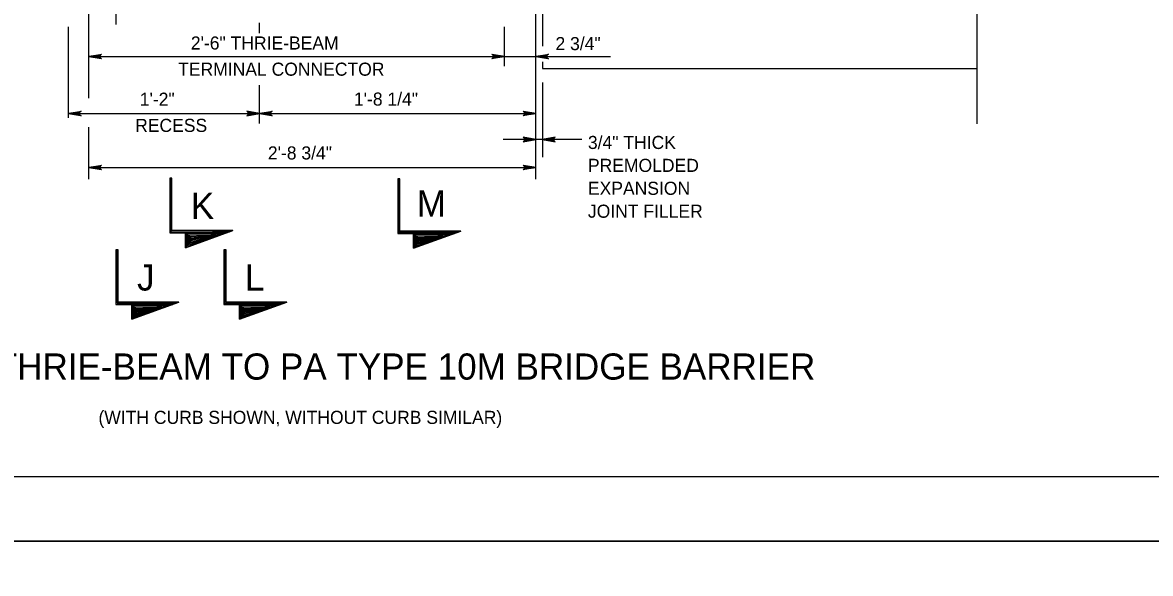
# Model space of a CAD drawing. Extents: x 632007860 to 635435983, y 295418622 to 297794622.
# Drawn here: x 633850541 to 634113016, y 296599122 to 296727373 of the extents above; entities that cross this region are included whole.
import ezdxf

# ---------------------------------------------------------------- set-up
doc = ezdxf.new("R2010")
doc.units = 0
for name, color, linetype in [('1', 7, 'Continuous'), ('PLT-BNDY', 7, 'Continuous'), ('S-DETL-DIMS', 7, 'Continuous'), ('S-DETL-T120', 7, 'Continuous'), ('S-DETL-T240', 7, 'Continuous'), ('S-STEL', 7, 'Continuous')]:
    doc.layers.add(name, color=color, linetype=linetype)

msp = doc.modelspace()

# ---------------------------------------------------------------- linework, layer by layer
at = {"layer": '1'}
msp.add_line((634515860, 296621622), (633729860, 296621622), dxfattribs=at)
at = {"layer": 'PLT-BNDY'}
for points in [[(633689860, 297200622), (634530860, 297200622), (634530860, 296606622), (633689860, 296606622)], [(633689860, 296606622), (634530860, 296606622), (634530860, 296012622), (633689860, 296012622)]]:
    msp.add_lwpolyline(points, close=True, dxfattribs=at)
at = {"layer": 'S-DETL-DIMS'}
for p, q in [((634072704, 296703831), (634072704, 296795863)), ((633865978, 296709782), (633865978, 296763351)), ((633872329, 296726956), (633872329, 296752996)), ((633969961, 296690900), (633969961, 296752996)), ((633861214, 296705153), (633861214, 296726352)), ((633905667, 296724913), (633905667, 296727323)), ((633962703, 296717254), (633962703, 296726397)), ((633865978, 296719492), (633987373, 296719492)), ((633905667, 296703838), (633905667, 296712782)), ((633971555, 296713419), (633971555, 296696042)), ((633861214, 296706192), (633969961, 296706192)), ((633865978, 296690900), (633865978, 296703032)), ((633980729, 296700162), (633962386, 296700162)), ((633865978, 296693644), (633969961, 296693644))]:
    msp.add_line(p, q, dxfattribs=at)
for points in [[(633865978, 296719492), (633868937, 296720047), (633868823, 296719968), (633868709, 296719889), (633868651, 296719790), (633868592, 296719690), (633868575, 296719591), (633868558, 296719492), (633868575, 296719393), (633868592, 296719294), (633868651, 296719194), (633868709, 296719095), (633868823, 296719016), (633868937, 296718937), (633865978, 296719492), (633868823, 296719016), (633868709, 296719095), (633865978, 296719492), (633868651, 296719194), (633868592, 296719294), (633865978, 296719492), (633868575, 296719393), (633868558, 296719492), (633865978, 296719492), (633868575, 296719591), (633868592, 296719690), (633865978, 296719492), (633868651, 296719790), (633868709, 296719889), (633865978, 296719492), (633868823, 296719968)], [(633962703, 296719492), (633959744, 296718937), (633959858, 296719016), (633959972, 296719095), (633960031, 296719194), (633960089, 296719294), (633960106, 296719393), (633960123, 296719492), (633960106, 296719591), (633960089, 296719690), (633960031, 296719790), (633959972, 296719889), (633959858, 296719968), (633959744, 296720047), (633962703, 296719492), (633959858, 296719968), (633959972, 296719889), (633962703, 296719492), (633960031, 296719790), (633960089, 296719690), (633962703, 296719492), (633960106, 296719591), (633960123, 296719492), (633962703, 296719492), (633960106, 296719393), (633960089, 296719294), (633962703, 296719492), (633960031, 296719194), (633959972, 296719095), (633962703, 296719492), (633959858, 296719016)], [(633969961, 296719492), (633972920, 296720047), (633972806, 296719968), (633972692, 296719889), (633972633, 296719790), (633972575, 296719690), (633972558, 296719591), (633972541, 296719492), (633972558, 296719393), (633972575, 296719294), (633972633, 296719194), (633972692, 296719095), (633972806, 296719016), (633972920, 296718937), (633969961, 296719492), (633972806, 296719016), (633972692, 296719095), (633969961, 296719492), (633972633, 296719194), (633972575, 296719294), (633969961, 296719492), (633972558, 296719393), (633972541, 296719492), (633969961, 296719492), (633972558, 296719591), (633972575, 296719690), (633969961, 296719492), (633972633, 296719790), (633972692, 296719889), (633969961, 296719492), (633972806, 296719968)], [(633861214, 296706192), (633864174, 296706747), (633864060, 296706668), (633863946, 296706589), (633863887, 296706489), (633863828, 296706390), (633863811, 296706291), (633863794, 296706192), (633863811, 296706093), (633863828, 296705993), (633863887, 296705894), (633863946, 296705795), (633864060, 296705716), (633864174, 296705637), (633861214, 296706192), (633864060, 296705716), (633863946, 296705795), (633861214, 296706192), (633863887, 296705894), (633863828, 296705993), (633861214, 296706192), (633863811, 296706093), (633863794, 296706192), (633861214, 296706192), (633863811, 296706291), (633863828, 296706390), (633861214, 296706192), (633863887, 296706489), (633863946, 296706589), (633861214, 296706192), (633864060, 296706668)], [(633905667, 296706192), (633902708, 296706747), (633902822, 296706668), (633902936, 296706589), (633902995, 296706489), (633903053, 296706390), (633903070, 296706291), (633903087, 296706192), (633903070, 296706093), (633903053, 296705993), (633902995, 296705894), (633902936, 296705795), (633902822, 296705716), (633902708, 296705637), (633905667, 296706192), (633902822, 296705716), (633902936, 296705795), (633905667, 296706192), (633902995, 296705894), (633903053, 296705993), (633905667, 296706192), (633903070, 296706093), (633903087, 296706192), (633905667, 296706192), (633903070, 296706291), (633903053, 296706390), (633905667, 296706192), (633902995, 296706489), (633902936, 296706589), (633905667, 296706192), (633902822, 296706668)], [(633905667, 296706192), (633908626, 296706747), (633908512, 296706668), (633908398, 296706589), (633908339, 296706489), (633908281, 296706390), (633908264, 296706291), (633908247, 296706192), (633908264, 296706093), (633908281, 296705993), (633908339, 296705894), (633908398, 296705795), (633908512, 296705716), (633908626, 296705637), (633905667, 296706192), (633908512, 296705716), (633908398, 296705795), (633905667, 296706192), (633908339, 296705894), (633908281, 296705993), (633905667, 296706192), (633908264, 296706093), (633908247, 296706192), (633905667, 296706192), (633908264, 296706291), (633908281, 296706390), (633905667, 296706192), (633908339, 296706489), (633908398, 296706589), (633905667, 296706192), (633908512, 296706668)], [(633969961, 296706192), (633967002, 296705637), (633967116, 296705716), (633967230, 296705795), (633967288, 296705894), (633967347, 296705993), (633967364, 296706093), (633967381, 296706192), (633967364, 296706291), (633967347, 296706390), (633967288, 296706489), (633967230, 296706589), (633967116, 296706668), (633967002, 296706747), (633969961, 296706192), (633967116, 296706668), (633967230, 296706589), (633969961, 296706192), (633967288, 296706489), (633967347, 296706390), (633969961, 296706192), (633967364, 296706291), (633967381, 296706192), (633969961, 296706192), (633967364, 296706093), (633967347, 296705993), (633969961, 296706192), (633967288, 296705894), (633967230, 296705795), (633969961, 296706192), (633967116, 296705716)], [(633969961, 296700162), (633967002, 296700717), (633967116, 296700638), (633967230, 296700559), (633967288, 296700459), (633967347, 296700360), (633967364, 296700261), (633967381, 296700162), (633967364, 296700063), (633967347, 296699963), (633967288, 296699864), (633967230, 296699765), (633967116, 296699686), (633967002, 296699607), (633969961, 296700162), (633967116, 296699686), (633967230, 296699765), (633969961, 296700162), (633967288, 296699864), (633967347, 296699963), (633969961, 296700162), (633967364, 296700063), (633967381, 296700162), (633969961, 296700162), (633967364, 296700261), (633967347, 296700360), (633969961, 296700162), (633967288, 296700459), (633967230, 296700559), (633969961, 296700162), (633967116, 296700638)], [(633971555, 296700162), (633974515, 296699607), (633974401, 296699686), (633974287, 296699765), (633974228, 296699864), (633974169, 296699963), (633974152, 296700063), (633974135, 296700162), (633974152, 296700261), (633974169, 296700360), (633974228, 296700459), (633974287, 296700559), (633974401, 296700638), (633974515, 296700717), (633971555, 296700162), (633974401, 296700638), (633974287, 296700559), (633971555, 296700162), (633974228, 296700459), (633974169, 296700360), (633971555, 296700162), (633974152, 296700261), (633974135, 296700162), (633971555, 296700162), (633974152, 296700063), (633974169, 296699963), (633971555, 296700162), (633974228, 296699864), (633974287, 296699765), (633971555, 296700162), (633974401, 296699686)], [(633865978, 296693644), (633868937, 296694198), (633868823, 296694119), (633868709, 296694040), (633868651, 296693941), (633868592, 296693842), (633868575, 296693743), (633868558, 296693644), (633868575, 296693544), (633868592, 296693445), (633868651, 296693346), (633868709, 296693247), (633868823, 296693168), (633868937, 296693089), (633865978, 296693644), (633868823, 296693168), (633868709, 296693247), (633865978, 296693644), (633868651, 296693346), (633868592, 296693445), (633865978, 296693644), (633868575, 296693544), (633868558, 296693644), (633865978, 296693644), (633868575, 296693743), (633868592, 296693842), (633865978, 296693644), (633868651, 296693941), (633868709, 296694040), (633865978, 296693644), (633868823, 296694119)], [(633969961, 296693644), (633967002, 296693089), (633967116, 296693168), (633967230, 296693247), (633967288, 296693346), (633967347, 296693445), (633967364, 296693544), (633967381, 296693644), (633967364, 296693743), (633967347, 296693842), (633967288, 296693941), (633967230, 296694040), (633967116, 296694119), (633967002, 296694198), (633969961, 296693644), (633967116, 296694119), (633967230, 296694040), (633969961, 296693644), (633967288, 296693941), (633967347, 296693842), (633969961, 296693644), (633967364, 296693743), (633967381, 296693644), (633969961, 296693644), (633967364, 296693544), (633967347, 296693445), (633969961, 296693644), (633967288, 296693346), (633967230, 296693247), (633969961, 296693644), (633967116, 296693168)], [(633885040, 296691118), (633885040, 296678683), (633898732, 296678683), (633899459, 296678947), (633885305, 296678947), (633885305, 296691118), (633884776, 296691118), (633884776, 296678418), (633898005, 296678418), (633888480, 296674951), (633888480, 296678418), (633899459, 296678947), (633888821, 296675377), (633888798, 296678164), (633896929, 296678255), (633889108, 296675744), (633889108, 296677866), (633895301, 296677957), (633889406, 296676122), (633889417, 296677544), (633894223, 296677785), (633889692, 296676524), (633889704, 296677281), (633892801, 296677533), (633889945, 296676787), (633889979, 296677109), (633891665, 296677304), (633889951, 296676946), (633888480, 296674951), (633888480, 296678418), (633889979, 296677109), (633899459, 296678947)], [(633938102, 296690993), (633938102, 296678558), (633951793, 296678558), (633952520, 296678823), (633938366, 296678823), (633938366, 296690993), (633937837, 296690993), (633937837, 296678293), (633951066, 296678293), (633941541, 296674827), (633941541, 296678293), (633952520, 296678823), (633941882, 296675252), (633941859, 296678039), (633949991, 296678131), (633942169, 296675619), (633942169, 296677741), (633948362, 296677833), (633942467, 296675998), (633942479, 296677420), (633947284, 296677661), (633942754, 296676399), (633942765, 296677156), (633945862, 296677408), (633943006, 296676663), (633943041, 296676984), (633944726, 296677179), (633943012, 296676821), (633941541, 296674827), (633941541, 296678293), (633943041, 296676984), (633952520, 296678823)], [(633872523, 296674455), (633872523, 296662019), (633886214, 296662019), (633886941, 296662284), (633872787, 296662284), (633872787, 296674455), (633872258, 296674455), (633872258, 296661755), (633885487, 296661755), (633875962, 296658288), (633875962, 296661755), (633886941, 296662284), (633876303, 296658713), (633876280, 296661500), (633884412, 296661592), (633876590, 296659080), (633876590, 296661202), (633882783, 296661294), (633876888, 296659459), (633876900, 296660881), (633881705, 296661122), (633877175, 296659860), (633877186, 296660617), (633880283, 296660869), (633877427, 296660124), (633877462, 296660445), (633879147, 296660640), (633877433, 296660282), (633875962, 296658288), (633875962, 296661755), (633877462, 296660445), (633886941, 296662284)], [(633897625, 296674455), (633897625, 296662019), (633911316, 296662019), (633912043, 296662284), (633897889, 296662284), (633897889, 296674455), (633897360, 296674455), (633897360, 296661755), (633910589, 296661755), (633901064, 296658288), (633901064, 296661755), (633912043, 296662284), (633901405, 296658713), (633901382, 296661500), (633909514, 296661592), (633901692, 296659080), (633901692, 296661202), (633907885, 296661294), (633901990, 296659459), (633902001, 296660881), (633906807, 296661122), (633902277, 296659860), (633902288, 296660617), (633905385, 296660869), (633902529, 296660124), (633902563, 296660445), (633904249, 296660640), (633902535, 296660282), (633901064, 296658288), (633901064, 296661755), (633902563, 296660445), (633912043, 296662284)]]:
    msp.add_lwpolyline(points, dxfattribs=at)
for points in [[(633885305, 296691118), (633884776, 296691118), (633884776, 296678418), (633888480, 296678418), (633888480, 296674951), (633899459, 296678947), (633885305, 296678947)], [(633938366, 296690993), (633937837, 296690993), (633937837, 296678293), (633941541, 296678293), (633941541, 296674827), (633952520, 296678823), (633938366, 296678823)], [(633872787, 296674455), (633872258, 296674455), (633872258, 296661755), (633875962, 296661755), (633875962, 296658288), (633886941, 296662284), (633872787, 296662284)], [(633897889, 296674455), (633897360, 296674455), (633897360, 296661755), (633901064, 296661755), (633901064, 296658288), (633912043, 296662284), (633897889, 296662284)]]:
    msp.add_lwpolyline(points, close=True, dxfattribs=at)
at = {"layer": 'S-STEL'}
for p, q in [((633971555, 296754701), (633971555, 296721897)), ((633971555, 296718225), (633971555, 296716643)), ((633971555, 296716643), (634072704, 296716643))]:
    msp.add_line(p, q, dxfattribs=at)

# ---------------------------------------------------------------- texts
at = {"layer": 'S-DETL-T120'}
for s, height, p in [('2\'-6" THRIE-BEAM', 3048.01, (633889705, 296721088)), ('2 3/4"', 3048, (633974558, 296720952)), ('TERMINAL CONNECTOR', 3048.01, (633886753, 296714992)), ('1\'-2"', 3048, (633877822, 296708004)), ('1\'-8 1/4"', 3048, (633927656, 296708035)), ('RECESS', 3048, (633876742, 296701908)), ('3/4" THICK ', 3048.07, (633982109, 296697935)), ('2\'-8 3/4"', 3048, (633907633, 296695497)), ('PREMOLDED ', 3048.1, (633982109, 296692601)), ('EXPANSION ', 3048.1, (633982109, 296687266)), ('JOINT FILLER', 3048.07, (633982109, 296681932)), ('(WITH CURB SHOWN, WITHOUT CURB SIMILAR)', 3048.01, (633868202, 296633935))]:
    msp.add_text(s, height=height, dxfattribs=at).set_placement(p)
at = {"layer": 'S-DETL-T240'}
for s, p in [('K', (633889694, 296681639)), ('M', (633942276, 296682184)), ('J', (633877177, 296664976)), ('L', (633902278, 296664976)), ('ELEVATION VIEW FOR THRIE-BEAM TO PA TYPE 10M BRIDGE BARRIER', (633753738, 296644243))]:
    msp.add_text(s, height=6096, dxfattribs=at).set_placement(p)

doc.saveas('drawing.dxf')
